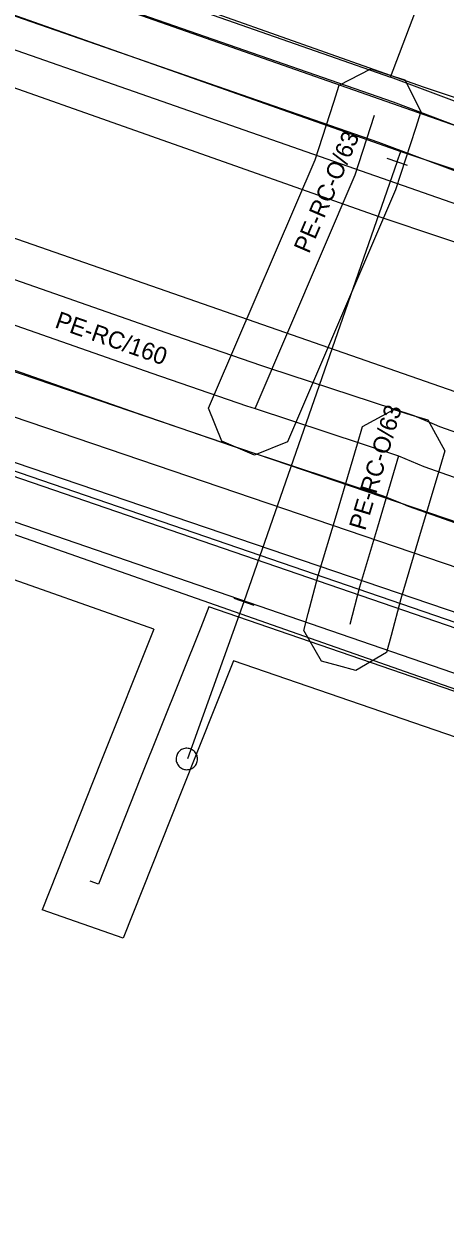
# Model space of a CAD drawing. Extents: x -762993 to -761845, y -975230 to -974501.
# Drawn here: x -762359.36 to -762349.52, y -974989.84 to -974962.16 of the extents above; entities that cross this region are included whole.
import ezdxf

# ---------------------------------------------------------------- set-up
doc = ezdxf.new("R2010")
doc.units = 0
for name, color, linetype in [('IS_CETIN_OP', 7, 'Continuous'), ('IS_CETIN_podzem metalika zam', 7, 'Continuous'), ('IS_CETIN_podzem NN', 7, 'Continuous'), ('IS_CETIN_podzem optika zam', 7, 'Continuous'), ('IS_CETIN_podzem out of order', 7, 'Continuous'), ('IS_CEZ-D_el vedeni NN podzem', 7, 'Continuous'), ('IS_CEZ-D_el vedeni VN podzem', 7, 'Continuous'), ('IS_CEZ-D_OP', 7, 'Continuous'), ('IS_CRA_podzem telekomunikace', 7, 'Continuous'), ('IS_DPmUL_OP', 7, 'Continuous'), ('IS_DPmUL_VO vedeni podzem', 7, 'Continuous'), ('IS_GASNET_plyn NTL anotace', 7, 'Continuous'), ('IS_GASNET_plyn NTL pripojky', 7, 'Continuous'), ('IS_GASNET_plyn NTL rad', 7, 'Continuous'), ('IS_GASNET_plyn OP', 7, 'Continuous'), ('IS_SCVK_kanalizace jednotna', 7, 'Continuous'), ('IS_SCVK_vodovod OP', 7, 'Continuous'), ('IS_SCVK_vodovod pripojky', 7, 'Continuous'), ('IS_SCVK_vodovod privadec', 7, 'Continuous'), ('IS_SCVK_vodovod znaky', 7, 'Continuous')]:
    doc.layers.add(name, color=color, linetype=linetype)

msp = doc.modelspace()

# ---------------------------------------------------------------- linework, layer by layer
at = {"layer": 'IS_CETIN_OP'}
msp.add_lwpolyline([(-762419.297, -974940.826), (-762417.443, -974941.715), (-762392.53, -974950.444), (-762377.95, -974955.514), (-762367.103, -974959.323), (-762363.702, -974960.533), (-762351.079, -974964.921), (-762349.293, -974965.589), (-762339.728, -974969), (-762336.376, -974970.461), (-762334.711, -974971.047)], dxfattribs=at)
at = {"layer": 'IS_CETIN_podzem metalika zam'}
msp.add_lwpolyline([(-762350.8, -974963.4), (-762348.1, -974956.3)], dxfattribs=at)
at = {"layer": 'IS_CETIN_podzem NN'}
for points in [[(-762377.76, -974954.03), (-762363.6, -974958.98), (-762359.54, -974960.34), (-762350.8, -974963.4)], [(-762336, -974968.94), (-762350.8, -974963.4)]]:
    msp.add_lwpolyline(points, dxfattribs=at)
at = {"layer": 'IS_CETIN_podzem optika zam'}
for points in [[(-762377.76, -974954.03), (-762363.6, -974958.98), (-762359.54, -974960.34), (-762350.8, -974963.4)], [(-762377.62, -974954.57), (-762366.77, -974958.38), (-762363.37, -974959.59), (-762350.74, -974963.98), (-762348.95, -974964.65), (-762339.36, -974968.07), (-762336.01, -974969.53), (-762326.29, -974972.95), (-762323.74, -974973.76), (-762321.62, -974974.46), (-762319.68, -974975.34), (-762318.84, -974976.94), (-762306.74, -974981.28), (-762300.75, -974982.76), (-762292.38, -974985.64), (-762290.68, -974986.06), (-762288.13, -974984.96), (-762286.9, -974983.04), (-762287.05, -974982.43), (-762287.36, -974981.94), (-762286.89, -974981.98), (-762283.27, -974983.91), (-762274.13, -974988.8), (-762260.53, -974993.46)], [(-762336, -974968.94), (-762350.8, -974963.4)]]:
    msp.add_lwpolyline(points, dxfattribs=at)
at = {"layer": 'IS_CETIN_podzem out of order'}
for points in [[(-762377.04, -974956.66), (-762339.91, -974969.63), (-762327.23, -974974.06)], [(-762393.36, -974970.49), (-762394.76, -974970.05), (-762391.76, -974961.27), (-762386.9, -974962.9), (-762371.15, -974968.61), (-762342.91, -974978.3), (-762324.01, -974984.93), (-762322.43, -974985.48)]]:
    msp.add_lwpolyline(points, dxfattribs=at)
at = {"layer": 'IS_CEZ-D_el vedeni NN podzem'}
for points in [[(-762394.922, -974961.348), (-762366.691, -974971.325), (-762338.912, -974980.87), (-762333.235, -974982.66), (-762317.369, -974988.815), (-762313.901, -974990.502), (-762312.492, -974990.931), (-762308.55, -974979.749), (-762308.284, -974978.995), (-762308.259, -974979.004), (-762304.782, -974980.906), (-762293.136, -974984.559), (-762291.208, -974984.727), (-762288.899, -974984.279), (-762285.346, -974981.506), (-762284.881, -974980.325), (-762284.547, -974977.953), (-762290.432, -974954.683), (-762291.314, -974953.684), (-762291.816, -974954.174), (-762292.054, -974954.011)], [(-762312.434, -975011.429), (-762311.562, -975011.492), (-762311.55, -975011.669), (-762308.991, -975012.245), (-762308.787, -975011.452), (-762307.552, -975006.66), (-762307.854, -974999.844), (-762312.234, -974993.249), (-762317.513, -974989.187), (-762333.367, -974983.038), (-762339.038, -974981.25), (-762354.832, -974975.823), (-762355.035, -974975.753), (-762355.226, -974976.23), (-762356.629, -974979.736), (-762357.615, -974982.215), (-762357.804, -974982.149)]]:
    msp.add_lwpolyline(points, dxfattribs=at)
at = {"layer": 'IS_CEZ-D_el vedeni VN podzem'}
msp.add_lwpolyline([(-762322.36, -974987.09), (-762324.59, -974986.24), (-762328.28, -974985.04), (-762360.05, -974973.9), (-762363.79, -974972.56), (-762395.59, -974961.56), (-762398.7, -974960.48), (-762421.28, -974952.57), (-762425.16, -974951.24), (-762434.97, -974947.57)], dxfattribs=at)
at = {"layer": 'IS_CEZ-D_OP'}
for points in [[(-762356.318, -974976.268), (-762360.384, -974974.843), (-762364.122, -974973.503), (-762395.917, -974962.505), (-762399.029, -974961.424), (-762421.607, -974953.515), (-762425.497, -974952.181), (-762435.253, -974948.532)], [(-762425.326, -974953.474), (-762425.823, -974952.392), (-762424.284, -974951.508), (-762423.951, -974951.317), (-762421.468, -974950.868), (-762394.588, -974960.405), (-762366.362, -974970.381), (-762338.599, -974979.92), (-762332.903, -974981.716), (-762317.463, -974987.706)], [(-762356.318, -974976.268), (-762357.558, -974979.365), (-762358.93, -974982.815)], [(-762312.622, -975010.413), (-762310.623, -975010.557), (-762310.603, -975010.857), (-762309.718, -975011.056), (-762308.558, -975006.555), (-762308.841, -975000.166), (-762312.975, -974993.94), (-762318.009, -974990.067), (-762333.698, -974983.982), (-762339.351, -974982.2), (-762354.46, -974977.008), (-762355.7, -974980.107), (-762357.04, -974983.475), (-762358.93, -974982.815)]]:
    msp.add_lwpolyline(points, dxfattribs=at)
at = {"layer": 'IS_CRA_podzem telekomunikace'}
msp.add_lwpolyline([(-762286.963, -974982.858), (-762286.915, -974983.05), (-762288.133, -974984.967), (-762290.685, -974986.061), (-762292.389, -974985.635), (-762300.689, -974982.775), (-762306.75, -974981.275), (-762318.851, -974976.949), (-762319.685, -974975.352), (-762321.623, -974974.461), (-762323.743, -974973.764), (-762326.285, -974972.953), (-762335.993, -974969.53), (-762339.363, -974968.07), (-762348.947, -974964.652), (-762363.377, -974959.593), (-762377.637, -974954.573), (-762392.217, -974949.493), (-762417.036, -974940.799), (-762419.044, -974939.84), (-762421.242, -974939.701), (-762425.393, -974938.364)], dxfattribs=at)
at = {"layer": 'IS_DPmUL_OP'}
for points in [[(-762371.192, -974966.319), (-762342.187, -974976.181)], [(-762371.836, -974968.213), (-762342.831, -974978.075)]]:
    msp.add_lwpolyline(points, dxfattribs=at)
at = {"layer": 'IS_DPmUL_VO vedeni podzem'}
msp.add_lwpolyline([(-762371.514, -974967.266), (-762342.509, -974977.128)], dxfattribs=at)
at = {"layer": 'IS_GASNET_plyn NTL pripojky'}
for points in [[(-762353.96, -974971.13), (-762351.62, -974965.68), (-762351.17, -974964.29)], [(-762350.61, -974972.23), (-762351.1, -974973.89), (-762351.52, -974975.29), (-762351.75, -974976.16)]]:
    msp.add_lwpolyline(points, dxfattribs=at)
at = {"layer": 'IS_GASNET_plyn NTL rad'}
msp.add_lwpolyline([(-762416.145, -974949.855), (-762381.041, -974961.735), (-762378.19, -974962.7), (-762377.47, -974962.93), (-762377.29, -974962.99), (-762377.092, -974963.051), (-762377.03, -974963.07), (-762356.37, -974970.3), (-762354.158, -974971.062), (-762353.96, -974971.13), (-762350.61, -974972.23), (-762350.171, -974972.416), (-762350.02, -974972.48), (-762336.17, -974977.35), (-762335.29, -974977.64), (-762335.11, -974977.68), (-762305.627, -974988.849), (-762305.14, -974989.03), (-762304.73, -974989.2), (-762303.75, -974989.6), (-762303.207, -974990.005), (-762302.681, -974990.396), (-762302.34, -974990.65)], dxfattribs=at)
at = {"layer": 'IS_GASNET_plyn OP'}
for points in [[(-762376.718, -974962.12), (-762356.042, -974969.355), (-762353.833, -974970.116), (-762353.642, -974970.182), (-762350.258, -974971.293), (-762349.781, -974971.495), (-762349.659, -974971.547), (-762335.848, -974976.403), (-762335.024, -974976.675), (-762334.823, -974976.719), (-762305.276, -974987.913)], [(-762305.978, -974989.785), (-762335.397, -974978.641), (-762335.556, -974978.605), (-762336.492, -974978.297), (-762350.381, -974973.413), (-762350.561, -974973.337), (-762350.962, -974973.167), (-762354.278, -974972.078), (-762354.483, -974972.008), (-762356.698, -974971.245), (-762377.342, -974964.02)]]:
    msp.add_lwpolyline(points, dxfattribs=at)
for points in [[(-762355.042, -974971.116), (-762354.879, -974970.735), (-762352.557, -974965.328), (-762352.121, -974963.982), (-762351.993, -974963.588), (-762351.256, -974963.211), (-762350.862, -974963.339), (-762350.468, -974963.467), (-762350.091, -974964.204), (-762350.219, -974964.598), (-762350.683, -974966.032), (-762353.041, -974971.525), (-762353.205, -974971.905), (-762353.974, -974972.212), (-762354.355, -974972.049), (-762354.735, -974971.885)], [(-762349.534, -974972.116), (-762349.651, -974972.513), (-762350.142, -974974.175), (-762350.557, -974975.562), (-762350.783, -974976.416), (-762350.889, -974976.816), (-762351.605, -974977.233), (-762352.006, -974977.127), (-762352.406, -974977.021), (-762352.823, -974976.305), (-762352.717, -974975.904), (-762352.483, -974975.018), (-762352.058, -974973.605), (-762351.569, -974971.947), (-762351.452, -974971.55), (-762350.724, -974971.154), (-762350.327, -974971.271), (-762349.93, -974971.388)]]:
    msp.add_lwpolyline(points, close=True, dxfattribs=at)
at = {"layer": 'IS_SCVK_kanalizace jednotna'}
msp.add_lwpolyline([(-762373.865, -974962.18), (-762330.791, -974977.171)], dxfattribs=at)
at = {"layer": 'IS_SCVK_vodovod OP'}
for points in [[(-762370.788, -974956.301), (-762365.679, -974958.103), (-762364.905, -974958.37), (-762350.036, -974963.625), (-762347.061, -974964.615), (-762327.066, -974971.647), (-762323.688, -974972.721), (-762321.219, -974973.584), (-762302.563, -974980.135), (-762292.067, -974983.465), (-762286.179, -974984.538), (-762284.497, -974984.727), (-762283.191, -974984.34)], [(-762371.852, -974959.319), (-762366.733, -974961.125), (-762365.959, -974961.392), (-762351.074, -974966.651), (-762348.097, -974967.643), (-762328.082, -974974.681), (-762324.702, -974975.757), (-762322.277, -974976.604), (-762303.577, -974983.171), (-762292.841, -974986.577), (-762286.645, -974987.706), (-762284.209, -974987.979), (-762282.49, -974987.47)]]:
    msp.add_lwpolyline(points, dxfattribs=at)
at = {"layer": 'IS_SCVK_vodovod pripojky'}
for points in [[(-762350.646, -974965.372), (-762354.222, -974975.632)], [(-762354.222, -974975.632), (-762355.536, -974979.291)]]:
    msp.add_lwpolyline(points, dxfattribs=at)
at = {"layer": 'IS_SCVK_vodovod privadec'}
msp.add_lwpolyline([(-762371.32, -974957.81), (-762366.206, -974959.614), (-762365.432, -974959.881), (-762350.555, -974965.138), (-762347.579, -974966.129), (-762327.574, -974973.164), (-762324.195, -974974.239), (-762321.748, -974975.094), (-762303.07, -974981.653), (-762292.454, -974985.021), (-762286.412, -974986.122), (-762284.353, -974986.353), (-762281.669, -974985.558)], dxfattribs=at)
at = {"layer": 'IS_SCVK_vodovod znaky'}
for points in [[(-762350.646, -974965.372), (-762350.555, -974965.138)], [(-762350.882, -974965.289), (-762350.41, -974965.455)], [(-762354.458, -974975.549), (-762353.986, -974975.715)], [(-762355.799, -974979.269), (-762355.801, -974979.295)], [(-762355.799, -974979.269), (-762355.801, -974979.295)], [(-762355.795, -974979.243), (-762355.799, -974979.269)], [(-762355.795, -974979.243), (-762355.799, -974979.269)], [(-762355.787, -974979.218), (-762355.795, -974979.243)], [(-762355.787, -974979.218), (-762355.795, -974979.243)], [(-762355.777, -974979.194), (-762355.787, -974979.218)], [(-762355.777, -974979.194), (-762355.787, -974979.218)], [(-762355.765, -974979.17), (-762355.777, -974979.194)], [(-762355.765, -974979.17), (-762355.777, -974979.194)], [(-762355.751, -974979.149), (-762355.765, -974979.17)], [(-762355.751, -974979.149), (-762355.765, -974979.17)], [(-762355.734, -974979.128), (-762355.751, -974979.149)], [(-762355.734, -974979.128), (-762355.751, -974979.149)], [(-762355.716, -974979.11), (-762355.734, -974979.128)], [(-762355.716, -974979.11), (-762355.734, -974979.128)], [(-762355.696, -974979.094), (-762355.716, -974979.11)], [(-762355.696, -974979.094), (-762355.716, -974979.11)], [(-762355.673, -974979.08), (-762355.696, -974979.094)], [(-762355.673, -974979.08), (-762355.696, -974979.094)], [(-762355.65, -974979.069), (-762355.673, -974979.08)], [(-762355.65, -974979.069), (-762355.673, -974979.08)], [(-762355.625, -974979.06), (-762355.65, -974979.069)], [(-762355.625, -974979.06), (-762355.65, -974979.069)], [(-762355.599, -974979.052), (-762355.625, -974979.06)], [(-762355.599, -974979.052), (-762355.625, -974979.06)], [(-762355.573, -974979.049), (-762355.599, -974979.052)], [(-762355.573, -974979.049), (-762355.599, -974979.052)], [(-762355.548, -974979.048), (-762355.573, -974979.049)], [(-762355.548, -974979.048), (-762355.573, -974979.049)], [(-762355.521, -974979.05), (-762355.548, -974979.048)], [(-762355.521, -974979.05), (-762355.548, -974979.048)], [(-762355.496, -974979.054), (-762355.521, -974979.05)], [(-762355.496, -974979.054), (-762355.521, -974979.05)], [(-762355.47, -974979.061), (-762355.496, -974979.054)], [(-762355.47, -974979.061), (-762355.496, -974979.054)], [(-762355.446, -974979.071), (-762355.47, -974979.061)], [(-762355.446, -974979.071), (-762355.47, -974979.061)], [(-762355.423, -974979.083), (-762355.446, -974979.071)], [(-762355.423, -974979.083), (-762355.446, -974979.071)], [(-762355.402, -974979.097), (-762355.423, -974979.083)], [(-762355.402, -974979.097), (-762355.423, -974979.083)], [(-762355.381, -974979.114), (-762355.402, -974979.097)], [(-762355.381, -974979.114), (-762355.402, -974979.097)], [(-762355.363, -974979.133), (-762355.381, -974979.114)], [(-762355.363, -974979.133), (-762355.381, -974979.114)], [(-762355.346, -974979.154), (-762355.363, -974979.133)], [(-762355.346, -974979.154), (-762355.363, -974979.133)], [(-762355.333, -974979.176), (-762355.346, -974979.154)], [(-762355.333, -974979.176), (-762355.346, -974979.154)], [(-762355.321, -974979.199), (-762355.333, -974979.176)], [(-762355.321, -974979.199), (-762355.333, -974979.176)], [(-762355.312, -974979.223), (-762355.321, -974979.199)], [(-762355.312, -974979.223), (-762355.321, -974979.199)], [(-762355.306, -974979.249), (-762355.312, -974979.223)], [(-762355.306, -974979.249), (-762355.312, -974979.223)], [(-762355.302, -974979.275), (-762355.306, -974979.249)], [(-762355.302, -974979.275), (-762355.306, -974979.249)], [(-762355.301, -974979.301), (-762355.302, -974979.275)], [(-762355.301, -974979.301), (-762355.302, -974979.275)], [(-762355.801, -974979.295), (-762355.8, -974979.321)], [(-762355.801, -974979.295), (-762355.8, -974979.321)], [(-762355.8, -974979.321), (-762355.796, -974979.346)], [(-762355.8, -974979.321), (-762355.796, -974979.346)], [(-762355.796, -974979.346), (-762355.789, -974979.372)], [(-762355.796, -974979.346), (-762355.789, -974979.372)], [(-762355.789, -974979.372), (-762355.78, -974979.397)], [(-762355.789, -974979.372), (-762355.78, -974979.397)], [(-762355.78, -974979.397), (-762355.769, -974979.421)], [(-762355.78, -974979.397), (-762355.769, -974979.421)], [(-762355.769, -974979.421), (-762355.754, -974979.442)], [(-762355.769, -974979.421), (-762355.754, -974979.442)], [(-762355.754, -974979.442), (-762355.739, -974979.463)], [(-762355.754, -974979.442), (-762355.739, -974979.463)], [(-762355.739, -974979.463), (-762355.72, -974979.481)], [(-762355.739, -974979.463), (-762355.72, -974979.481)], [(-762355.72, -974979.481), (-762355.701, -974979.498)], [(-762355.72, -974979.481), (-762355.701, -974979.498)], [(-762355.701, -974979.498), (-762355.677, -974979.513)], [(-762355.701, -974979.498), (-762355.677, -974979.513)], [(-762355.677, -974979.513), (-762355.655, -974979.524)], [(-762355.677, -974979.513), (-762355.655, -974979.524)], [(-762355.655, -974979.524), (-762355.631, -974979.535)], [(-762355.655, -974979.524), (-762355.631, -974979.535)], [(-762355.631, -974979.535), (-762355.606, -974979.541)], [(-762355.631, -974979.535), (-762355.606, -974979.541)], [(-762355.606, -974979.541), (-762355.579, -974979.546)], [(-762355.606, -974979.541), (-762355.579, -974979.546)], [(-762355.579, -974979.546), (-762355.554, -974979.548)], [(-762355.579, -974979.546), (-762355.554, -974979.548)], [(-762355.554, -974979.548), (-762355.528, -974979.546)], [(-762355.554, -974979.548), (-762355.528, -974979.546)], [(-762355.528, -974979.546), (-762355.501, -974979.543)], [(-762355.528, -974979.546), (-762355.501, -974979.543)], [(-762355.501, -974979.543), (-762355.476, -974979.537)], [(-762355.501, -974979.543), (-762355.476, -974979.537)], [(-762355.476, -974979.537), (-762355.452, -974979.527)], [(-762355.476, -974979.537), (-762355.452, -974979.527)], [(-762355.452, -974979.527), (-762355.428, -974979.516)], [(-762355.452, -974979.527), (-762355.428, -974979.516)], [(-762355.428, -974979.516), (-762355.407, -974979.502)], [(-762355.428, -974979.516), (-762355.407, -974979.502)], [(-762355.407, -974979.502), (-762355.385, -974979.486)], [(-762355.407, -974979.502), (-762355.385, -974979.486)], [(-762355.385, -974979.486), (-762355.367, -974979.467)], [(-762355.385, -974979.486), (-762355.367, -974979.467)], [(-762355.367, -974979.467), (-762355.35, -974979.447)], [(-762355.367, -974979.467), (-762355.35, -974979.447)], [(-762355.35, -974979.447), (-762355.336, -974979.425)], [(-762355.35, -974979.447), (-762355.336, -974979.425)], [(-762355.336, -974979.425), (-762355.324, -974979.402)], [(-762355.336, -974979.425), (-762355.324, -974979.402)], [(-762355.324, -974979.402), (-762355.314, -974979.378)], [(-762355.324, -974979.402), (-762355.314, -974979.378)], [(-762355.314, -974979.378), (-762355.306, -974979.353)], [(-762355.314, -974979.378), (-762355.306, -974979.353)], [(-762355.306, -974979.353), (-762355.302, -974979.327)], [(-762355.306, -974979.353), (-762355.302, -974979.327)], [(-762355.302, -974979.327), (-762355.301, -974979.301)], [(-762355.302, -974979.327), (-762355.301, -974979.301)]]:
    msp.add_lwpolyline(points, dxfattribs=at)

# ---------------------------------------------------------------- texts
at = {"layer": 'IS_GASNET_plyn NTL anotace'}
for s, rotation, p in [('PE-RC-O/63', 66.7634, (-762352.702, -974967.534)), ('PE-RC/160', 340.7124, (-762358.652, -974969.231)), ('PE-RC-O/63', 73.3008, (-762351.391, -974973.992))]:
    msp.add_text(s, height=0.4, rotation=rotation, dxfattribs=at).set_placement(p)

doc.saveas('drawing.dxf')
